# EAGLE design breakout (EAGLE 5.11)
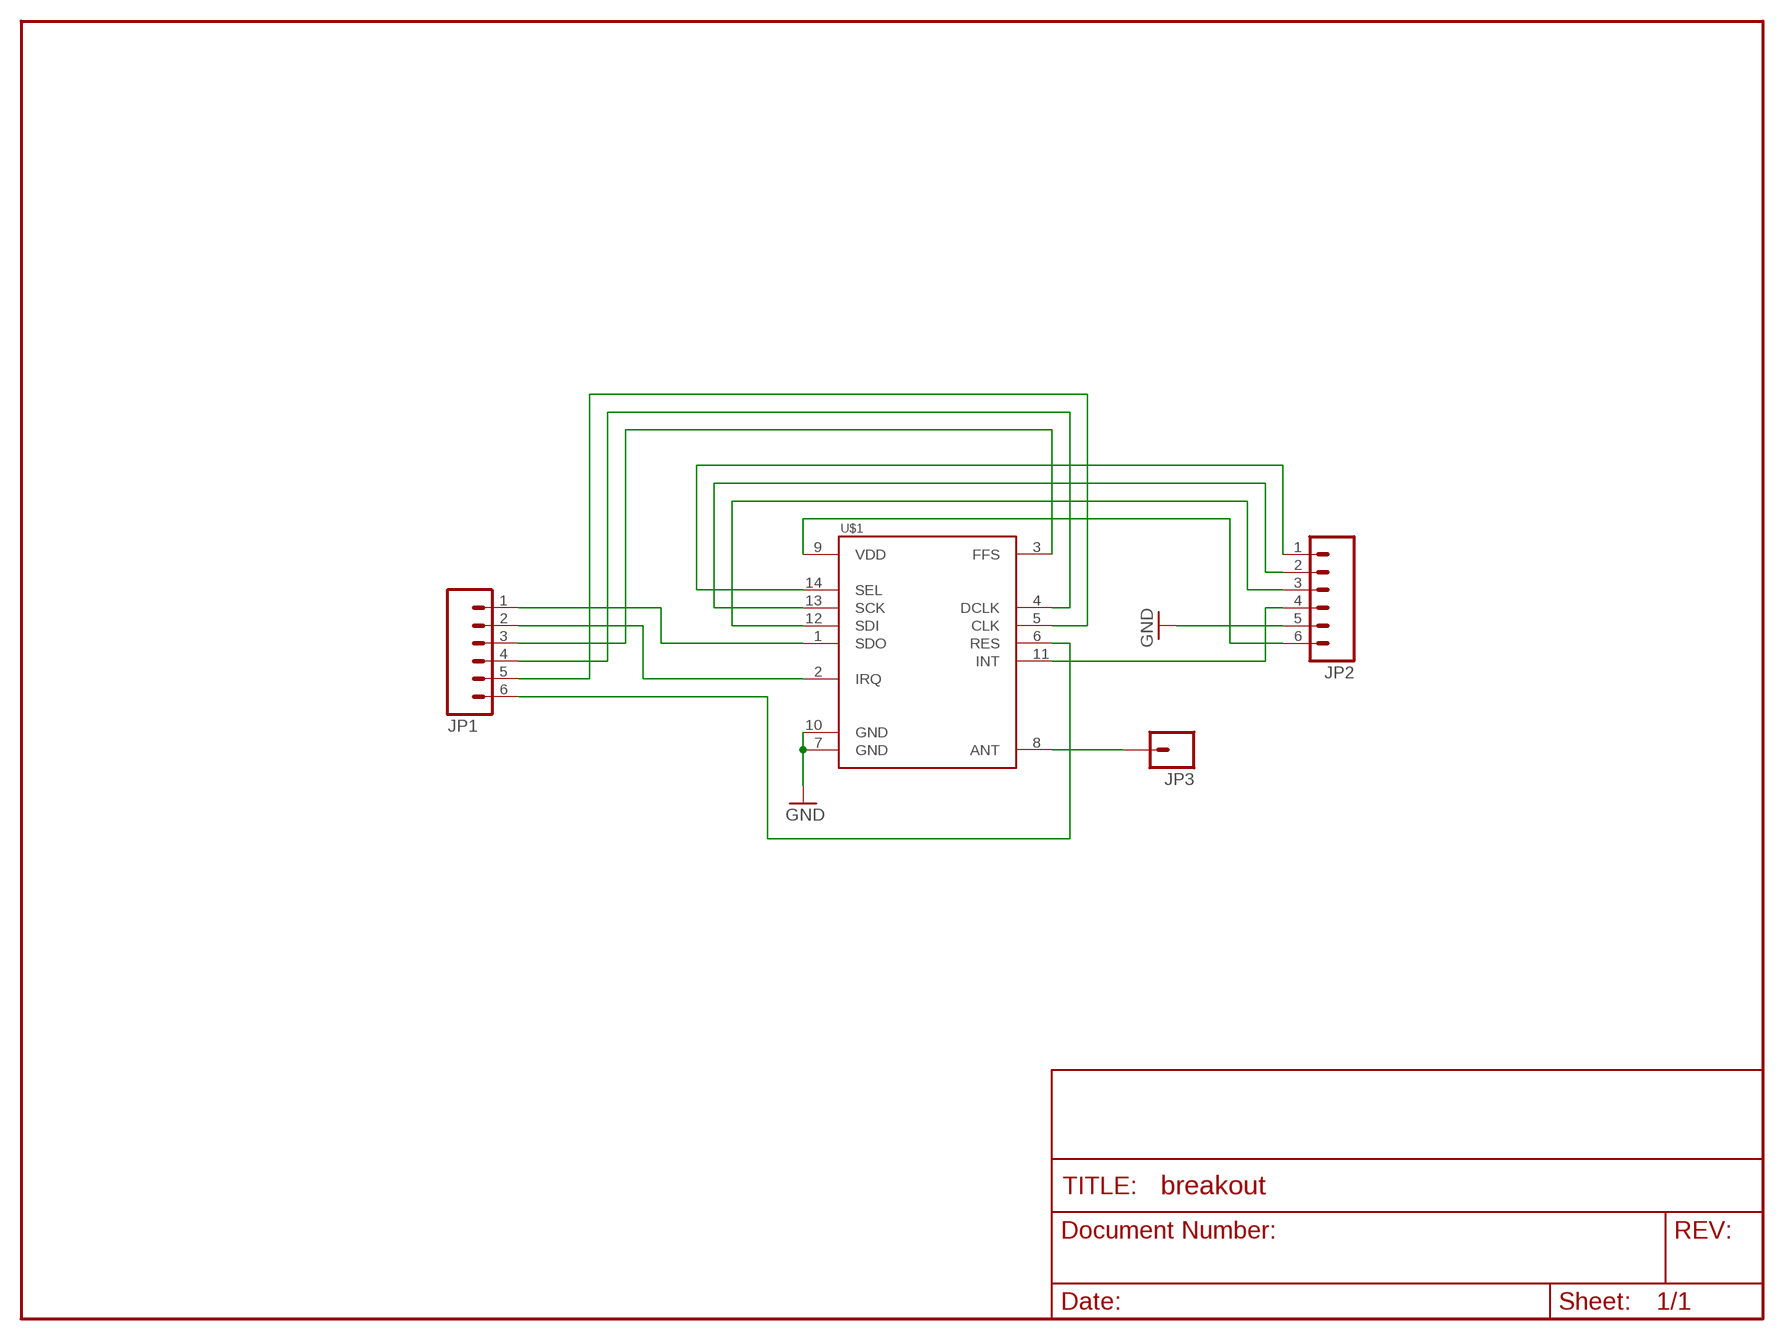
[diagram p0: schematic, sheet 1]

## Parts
JP1  M06SIP  [1X06]
JP2  M06SIP  [1X06]
JP3  M01PTH_LONGPAD  [1X01_LONGPAD]
U$1  RFM12BS  [RFM12SB]

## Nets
GND: JP2.5 U$1.7(GND) U$1.10(GND)
N$1: JP3.1 U$1.8(ANT)
N$2: JP1.1 U$1.1(SDO)
N$3: JP1.2 U$1.2(IRQ)
N$4: JP1.3 U$1.3(FFS)
N$5: JP1.4 U$1.4(DCLK)
N$6: JP1.5 U$1.5(CLK)
N$9: JP2.1 U$1.14(SEL)
N$10: JP2.2 U$1.13(SCK)
N$11: JP2.3 U$1.12(SDI)
N$12: JP2.4 U$1.11(INT)
N$13: JP2.6 U$1.9(VDD)
N$14: JP1.6 U$1.6(RES)

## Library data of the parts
JP1 JP2 = SparkFun:M06: Header 6 Standard 6-pin 0.1" header. Use with straight break away headers (SKU : PRT-00116), right angle break away headers (PRT-00553), swiss pins (PRT-00743), machine pins (PRT-00117), and female headers (PRT-00115). Molex polarized connector foot print use with SKU : PRT-08094 with associated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
JP3 = SparkFun:M01: Header 1
U$1 = Tropotek:RFM12BS

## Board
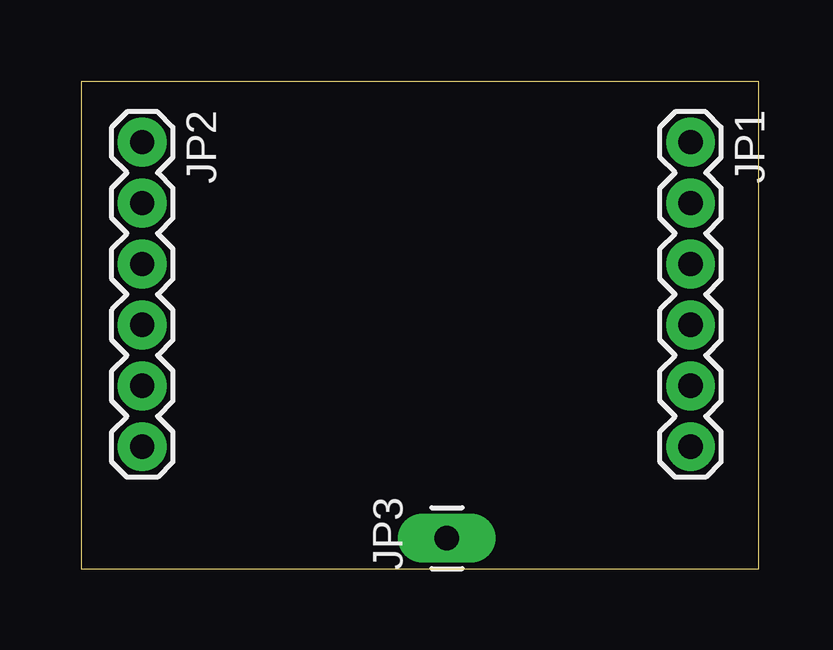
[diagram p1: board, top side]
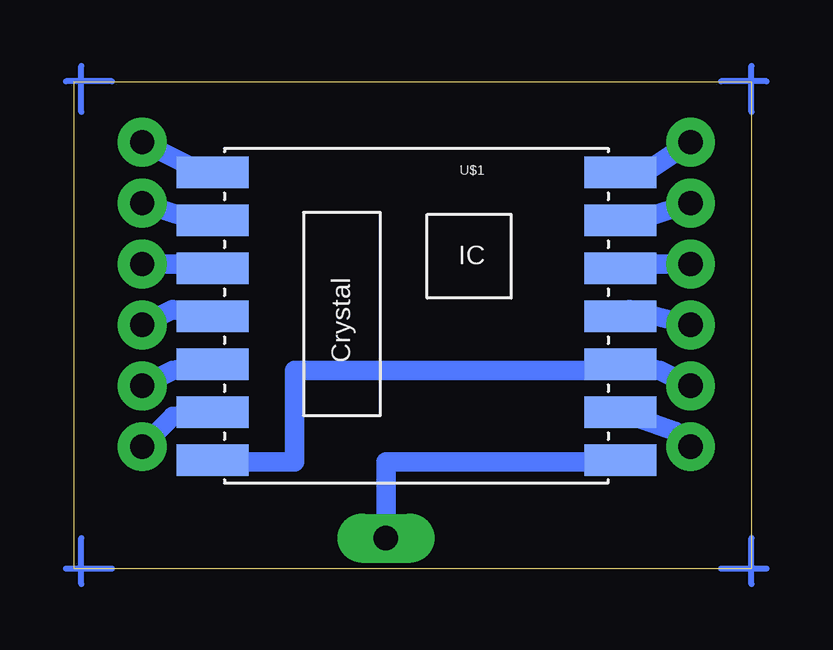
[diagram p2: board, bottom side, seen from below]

Size 28.25 x 20.31 mm. Coordinates in mm from the lower left corner, seen from the top.
Outline: 0,0 28.25,0 28.25,20.31 0,20.31 0,0
Copper layers (1*16): Top 0.035mm / dielectric 1.5mm / Bottom 0.035mm
Design rules "home1 *": minimum track width 20mil, minimum drill 25mil, track to track 10mil, track to pad 10mil, pad to pad 10mil, via to via 10mil, smd to smd 10mil, copper to edge 40mil, drill to drill 10mil, minimum pad ring 20mil, minimum via ring 10mil, stop-mask expansion 8mil, vias tented up to drill 0mil, thermal gap 10mil

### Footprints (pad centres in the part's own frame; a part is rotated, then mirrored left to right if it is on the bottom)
1X06 = drill 1.016 pad 1.88 round: 1 0,0; 2 2.54,0; 3 5.08,0; 4 7.62,0; 5 10.16,0; 6 12.7,0
1X01_LONGPAD = drill 1.016 pad 1.88 long: 1 0,0
RFM12SB = smd 3 x 1.3: 1 -8.5,7; 2 -8.5,5; 3 -8.5,3; 4 -8.5,1; 5 -8.5,-1; 6 -8.5,-3; 7 -8.5,-5; 8 8.5,-5; 9 8.5,-3; 10 8.5,-1; 11 8.5,1; 12 8.5,3; 13 8.5,5; 14 8.5,7

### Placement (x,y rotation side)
JP1  25.4,17.78 270 top
JP2  2.54,17.78 270 top
JP3  15.24,1.27 90 top
U$1  13.97,9.53 0 bottom

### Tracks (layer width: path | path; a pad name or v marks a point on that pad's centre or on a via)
GND
  Bottom 0.61: 22.23,4.45 22.3,4.53 U$1.7 | U$1.10 5.47,8.5 5.71,8.26
  Bottom 0.813: 22.23,4.45 19.05,4.45 19.05,8.26 5.71,8.26 | JP2.5 3.81,8.26 U$1.10
N$1
  Bottom 0.381: 5.63,4.53 5.71,4.45
  Bottom 0.813: U$1.8 5.63,4.53 | 5.71,4.45 15.24,4.45 JP3.1
N$2
  Bottom 0.813: JP1.1 22.86,16.51 U$1.1
N$3
  Bottom 0.813: U$1.2 23.5,14.61 JP1.2
N$4
  Bottom 0.813: U$1.3 22.86,12.7 JP1.3
N$5
  Bottom 0.813: U$1.4 24.13,10.79 JP1.4
N$6
  Bottom 0.813: U$1.5 24.13,8.26 JP1.5
N$9
  Bottom 0.61: 4.45,16.51 U$1.14
  Bottom 0.813: JP2.1 4.45,16.51
N$10
  Bottom 0.813: U$1.13 4.45,14.61 JP2.2
N$11
  Bottom 0.813: U$1.12 4.45,12.7 JP2.3
N$12
  Bottom 0.813: JP2.4 5.08,10.79 U$1.11
N$13
  Bottom 0.813: U$1.9 3.17,5.71 JP2.6
N$14
  Bottom 0.813: U$1.6 24.13,6.35 JP1.6
N$15
  Bottom 0.254: 0,-0.64 0,1.27
N$16
  Bottom 0.254: -0.64,0 1.27,0
N$17
  Bottom 0.254: 26.67,0 28.57,0
N$18
  Bottom 0.254: 27.94,-0.64 27.94,1.27
N$19
  Bottom 0.254: 0,19.05 0,20.95
N$20
  Bottom 0.254: -0.64,20.32 1.27,20.32
N$21
  Bottom 0.254: 26.67,20.32 28.57,20.32
N$22
  Bottom 0.254: 27.94,19.05 27.94,20.95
